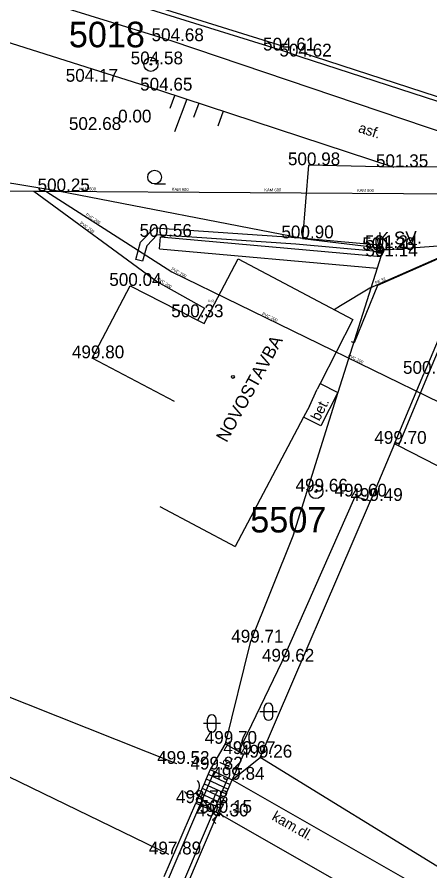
# Model space of a CAD drawing. Extents: x -668867 to -667827, y -1131943 to -1131019.
# Drawn here: x -668306.6 to -668282.4, y -1131620.9 to -1131570.8 of the extents above; entities that cross this region are included whole.
import ezdxf

# ---------------------------------------------------------------- set-up
doc = ezdxf.new("R2010")
doc.units = 0
for name, color, linetype in [('G_Bod_tecka', 7, 'Continuous'), ('G_Bod_vyska', 7, 'Continuous'), ('G_Bodove_pole', 7, 'Continuous'), ('G_Breh_Teren', 7, 'Continuous'), ('G_Budovy-znacky', 7, 'Continuous'), ('G_Budovy_Objekty', 7, 'Continuous'), ('G_Budovy_vstupy', 7, 'Continuous'), ('G_Cesty_Schody', 7, 'Continuous'), ('G_Plochy_zpevnene', 7, 'Continuous'), ('G_Ploty', 7, 'Continuous'), ('G_Ploty_vstupy', 7, 'Continuous'), ('G_Popisy_povrchu', 7, 'Continuous'), ('G_Poznamky_odkaz', 7, 'Continuous'), ('G_Site-kanalizace', 7, 'Continuous'), ('G_Site-Sloupy', 7, 'Continuous'), ('G_Vyskove_srafy', 7, 'Continuous'), ('G_Z_CHRANICKA-TEPLOVOD_kotovane', 7, 'Continuous'), ('G_Z_ELsilove_nadz_kotovane', 7, 'Continuous'), ('G_Z_KANAL_podz_kotovane', 7, 'Continuous'), ('G_Z_SPOJE_podz_geodeticky', 7, 'Continuous'), ('G_Z_SPOJE_podz_kotovane', 7, 'Continuous'), ('G_Z_SPOJE_podz_priblizne', 7, 'Continuous'), ('G_Z_VODA_podz_kotovane', 7, 'Continuous'), ('G_Zabradli_Svodidla', 7, 'Continuous'), ('G_Zelen-Znacky', 7, 'Continuous'), ('Vrstva 12', 7, 'Continuous'), ('Vrstva 13', 7, 'Continuous'), ('Vrstva 2', 7, 'Continuous'), ('Vrstva 26', 7, 'Continuous'), ('Vrstva 3', 7, 'Continuous'), ('Vrstva 4', 7, 'Continuous'), ('Vrstva 8', 7, 'Continuous')]:
    doc.layers.add(name, color=color, linetype=linetype)

msp = doc.modelspace()

# ---------------------------------------------------------------- linework, layer by layer
at = {"layer": 'G_Bod_tecka'}
for p, q in [((-668297.5, -1131572.23), (-668297.5, -1131572.23)), ((-668291.02, -1131572.78), (-668291.02, -1131572.78)), ((-668290, -1131573.13), (-668290, -1131573.13)), ((-668298.74, -1131573.59), (-668298.74, -1131573.59)), ((-668302.69, -1131574.61), (-668302.69, -1131574.61)), ((-668298.17, -1131575.13), (-668298.17, -1131575.13)), ((-668299.88, -1131577), (-668299.88, -1131577)), ((-668302.35, -1131577.44), (-668302.35, -1131577.44)), ((-668289.49, -1131579.51), (-668289.49, -1131579.51)), ((-668284.49, -1131579.62), (-668284.49, -1131579.62)), ((-668304.18, -1131581.04), (-668304.18, -1131581.04)), ((-668298.18, -1131583.71), (-668298.18, -1131583.71)), ((-668289.85, -1131583.8), (-668289.85, -1131583.8)), ((-668285.28, -1131584.49), (-668285.28, -1131584.49)), ((-668285.25, -1131584.86), (-668285.25, -1131584.86)), ((-668285.13, -1131584.37), (-668285.13, -1131584.37)), ((-668299.95, -1131586.59), (-668299.95, -1131586.59)), ((-668296.35, -1131588.43), (-668296.35, -1131588.43)), ((-668302.18, -1131590.84), (-668302.18, -1131590.84)), ((-668282.72, -1131591.75), (-668282.72, -1131591.75)), ((-668284.44, -1131595.86), (-668284.44, -1131595.86)), ((-668289.06, -1131598.66), (-668289.06, -1131598.66)), ((-668286.76, -1131598.95), (-668286.76, -1131598.95)), ((-668285.86, -1131599.21), (-668285.86, -1131599.21)), ((-668292.92, -1131607.52), (-668292.92, -1131607.52)), ((-668291.04, -1131608.64), (-668291.04, -1131608.64)), ((-668294.39, -1131613.46), (-668294.39, -1131613.46)), ((-668293.31, -1131614.06), (-668293.31, -1131614.06)), ((-668292.33, -1131614.27), (-668292.33, -1131614.27)), ((-668297.21, -1131614.64), (-668297.21, -1131614.64)), ((-668295.26, -1131614.97), (-668295.26, -1131614.97)), ((-668293.97, -1131615.57), (-668293.97, -1131615.57)), ((-668296.1, -1131616.94), (-668296.1, -1131616.94)), ((-668294.89, -1131617.72), (-668294.89, -1131617.72)), ((-668294.81, -1131617.51), (-668294.81, -1131617.51)), ((-668297.69, -1131619.95), (-668297.69, -1131619.95))]:
    msp.add_line(p, q, dxfattribs=at)
at = {"layer": 'G_Bodove_pole'}
for centre, radius in [((-668298.74, -1131573.59), 0.412), ((-668298.74, -1131573.59), 0.05), ((-668289.06, -1131598.66), 0.412), ((-668289.06, -1131598.66), 0.05)]:
    msp.add_circle(centre, radius, dxfattribs=at)
at = {"layer": 'G_Breh_Teren'}
for p, q in [((-668304.18, -1131581.04), (-668313.28, -1131579.52)), ((-668289.85, -1131583.8), (-668304.18, -1131581.04))]:
    msp.add_line(p, q, dxfattribs=at)
msp.add_lwpolyline([(-668297.69, -1131619.95), (-668307.08, -1131615.39), (-668316.46, -1131610.83), (-668321.53, -1131608.45), (-668329.23, -1131605.11), (-668337.01, -1131601.9), (-668340.19, -1131600.66), (-668345.82, -1131598.75), (-668354.38, -1131596.26), (-668362.99, -1131593.93), (-668371.08, -1131591.74)], dxfattribs=at)
at = {"layer": 'G_Budovy-znacky'}
msp.add_circle((-668293.93, -1131591.93), 0.0875, dxfattribs=at)
at = {"layer": 'G_Budovy_Objekty'}
for p, q in [((-668293.62, -1131585.01), (-668286.89, -1131588.57)), ((-668297.35, -1131593.38), (-668302.18, -1131590.84)), ((-668298.22, -1131599.54), (-668293.8, -1131601.88)), ((-668297.96, -1131621.25), (-668296.1, -1131616.94)), ((-668294.81, -1131617.51), (-668298.96, -1131627.18))]:
    msp.add_line(p, q, dxfattribs=at)
for points in [[(-668296.35, -1131588.43), (-668295.62, -1131588.8), (-668293.62, -1131585.01)], [(-668302.18, -1131590.84), (-668299.95, -1131586.59), (-668297.15, -1131588.02)], [(-668286.89, -1131588.57), (-668288.81, -1131592.32), (-668288.98, -1131592.65)], [(-668289.44, -1131593.64), (-668289.79, -1131594.3)], [(-668289.79, -1131594.3), (-668293.8, -1131601.88)]]:
    msp.add_lwpolyline(points, dxfattribs=at)
at = {"layer": 'G_Budovy_vstupy'}
for p, q in [((-668296.35, -1131588.43), (-668297.15, -1131588.02)), ((-668289.44, -1131593.64), (-668288.98, -1131592.65))]:
    msp.add_line(p, q, dxfattribs=at)
at = {"layer": 'G_Cesty_Schody'}
for p, q in [((-668297.5, -1131572.23), (-668314.35, -1131567)), ((-668315.47, -1131569.63), (-668298.17, -1131575.13))]:
    msp.add_line(p, q, dxfattribs=at)
for points in [[(-668295.37, -1131615.25), (-668295.49, -1131615.52)], [(-668295.26, -1131614.97), (-668295.37, -1131615.25)], [(-668295.37, -1131615.25), (-668294.09, -1131615.84)], [(-668295.26, -1131614.97), (-668293.97, -1131615.57)], [(-668295.61, -1131615.8), (-668295.73, -1131616.07)], [(-668295.49, -1131615.52), (-668295.61, -1131615.8)], [(-668295.61, -1131615.8), (-668294.33, -1131616.39)], [(-668295.49, -1131615.52), (-668294.21, -1131616.12)], [(-668294.21, -1131616.12), (-668294.09, -1131615.84)], [(-668294.09, -1131615.84), (-668293.97, -1131615.57)], [(-668295.85, -1131616.35), (-668295.96, -1131616.63)], [(-668295.73, -1131616.07), (-668295.85, -1131616.35)], [(-668295.85, -1131616.35), (-668294.57, -1131616.94)], [(-668295.73, -1131616.07), (-668294.45, -1131616.67)], [(-668294.45, -1131616.67), (-668294.33, -1131616.39)], [(-668294.33, -1131616.39), (-668294.21, -1131616.12)], [(-668295.96, -1131616.63), (-668296.1, -1131616.94)], [(-668295.96, -1131616.63), (-668294.69, -1131617.22)], [(-668294.57, -1131616.94), (-668294.45, -1131616.67)], [(-668296.1, -1131616.94), (-668294.81, -1131617.51)], [(-668294.81, -1131617.51), (-668294.69, -1131617.22)], [(-668294.69, -1131617.22), (-668294.57, -1131616.94)]]:
    msp.add_lwpolyline(points, dxfattribs=at)
at = {"layer": 'G_Plochy_zpevnene'}
for p, q in [((-668298.17, -1131575.13), (-668284.49, -1131579.62)), ((-668289.49, -1131579.51), (-668289.85, -1131583.8)), ((-668289.85, -1131583.8), (-668285.13, -1131584.37)), ((-668291.04, -1131608.64), (-668286.76, -1131598.95)), ((-668286.76, -1131598.95), (-668285.86, -1131599.21)), ((-668294.39, -1131613.46), (-668293.57, -1131613.91))]:
    msp.add_line(p, q, dxfattribs=at)
for points in [[(-668277.65, -1131578.66), (-668279.86, -1131578.2), (-668297.5, -1131572.23)], [(-668281.23, -1131579.62), (-668282.79, -1131579.61), (-668284.49, -1131579.62), (-668286.99, -1131579.56), (-668289.49, -1131579.51)], [(-668285.25, -1131584.86), (-668285.47, -1131585.55), (-668287.78, -1131592.84), (-668290.41, -1131601.28), (-668292.92, -1131607.52)], [(-668285.13, -1131584.37), (-668285.25, -1131584.86)], [(-668288.81, -1131592.32), (-668287.78, -1131592.84), (-668288.77, -1131594.81), (-668289.79, -1131594.3)], [(-668292.92, -1131607.52), (-668294.39, -1131613.46)], [(-668293.57, -1131613.91), (-668291.04, -1131608.64)], [(-668294.39, -1131613.46), (-668295.26, -1131614.97)], [(-668293.57, -1131613.91), (-668293.31, -1131614.06)], [(-668293.31, -1131614.06), (-668293.97, -1131615.57)], [(-668293.97, -1131615.57), (-668282.89, -1131621.91)], [(-668294.81, -1131617.51), (-668287.32, -1131621.79)]]:
    msp.add_lwpolyline(points, dxfattribs=at)
at = {"layer": 'G_Ploty'}
for p, q in [((-668290.95, -1131572.54), (-668315.71, -1131564.82)), ((-668315.78, -1131565.06), (-668291.02, -1131572.78)), ((-668290, -1131573.13), (-668278.48, -1131576.88)), ((-668278.49, -1131576.62), (-668289.92, -1131572.89)), ((-668298.24, -1131584.41), (-668298.18, -1131583.71)), ((-668298.18, -1131583.71), (-668285.25, -1131584.86)), ((-668298.24, -1131584.41), (-668285.47, -1131585.55)), ((-668279.64, -1131584.38), (-668282.72, -1131591.75)), ((-668282.49, -1131591.85), (-668279.45, -1131584.57)), ((-668284.44, -1131595.86), (-668282.72, -1131591.75)), ((-668284.22, -1131595.98), (-668282.49, -1131591.85)), ((-668284.22, -1131595.98), (-668284.44, -1131595.86)), ((-668275.6, -1131600.39), (-668284.22, -1131595.98)), ((-668292.33, -1131614.27), (-668285.86, -1131599.21)), ((-668297.21, -1131614.64), (-668308.73, -1131610.06)), ((-668293.97, -1131615.57), (-668292.33, -1131614.27)), ((-668264.03, -1131631.7), (-668292.33, -1131614.27))]:
    msp.add_line(p, q, dxfattribs=at)
at = {"layer": 'G_Ploty_vstupy'}
for p, q in [((-668291.02, -1131572.78), (-668290, -1131573.13)), ((-668284.44, -1131595.86), (-668285.86, -1131599.21))]:
    msp.add_line(p, q, dxfattribs=at)
at = {"layer": 'G_Site-kanalizace'}
for p, q in [((-668296.071, -1131616.313), (-668294.89, -1131617.72)), ((-668295.12, -1131617.913), (-668294.89, -1131617.72)), ((-668294.927, -1131618.143), (-668295.12, -1131617.913)), ((-668294.66, -1131617.527), (-668294.89, -1131617.72)), ((-668294.467, -1131617.757), (-668294.66, -1131617.527))]:
    msp.add_line(p, q, dxfattribs=at)
msp.add_arc((-668296.393, -1131615.931), 0.5, 220.0084, 40.0084, dxfattribs=at)
at = {"layer": 'G_Site-Sloupy'}
msp.add_circle((-668285.28, -1131584.49), 0.2, dxfattribs=at)
for radius in [0.18, 0.16, 0.14, 0.12, 0.1, 0.08, 0.06, 0.04, 0.02]:
    msp.add_arc((-668285.28, -1131584.49), radius, 180, 0, dxfattribs=at)
at = {"layer": 'G_Vyskove_srafy'}
for p, q in [((-668297.36, -1131575.43), (-668297.63, -1131576.18)), ((-668296.63, -1131575.63), (-668297.35, -1131577.56)), ((-668295.92, -1131575.87), (-668296.23, -1131576.7)), ((-668294.49, -1131576.34), (-668294.82, -1131577.22))]:
    msp.add_line(p, q, dxfattribs=at)
at = {"layer": 'G_Z_CHRANICKA-TEPLOVOD_kotovane'}
msp.add_lwpolyline([(-668299.624, -1131585.032), (-668299.339, -1131584.027), (-668298.519, -1131583.174), (-668290.194, -1131583.751), (-668285.594, -1131584.153), (-668285.208, -1131584.302), (-668285.352, -1131584.676), (-668285.686, -1131584.547), (-668290.226, -1131584.149), (-668298.361, -1131583.586), (-668298.981, -1131584.233), (-668299.239, -1131585.141)], close=True, dxfattribs=at)
at = {"layer": 'G_Z_ELsilove_nadz_kotovane'}
for points in [[(-668285.28, -1131584.49), (-668266.27, -1131583.06)], [(-668285.28, -1131584.49), (-668285.452, -1131583.853)]]:
    msp.add_lwpolyline(points, dxfattribs=at)
at = {"layer": 'G_Z_KANAL_podz_kotovane'}
for points in [[(-668311.3, -1131581), (-668305.6, -1131581.03), (-668304.9, -1131581.04), (-668280.93, -1131581.18)], [(-668305.6, -1131581.03), (-668298.35, -1131586.35), (-668295.59, -1131587.89), (-668296, -1131588.62)], [(-668304.9, -1131581.04), (-668297.51, -1131585.77), (-668273.92, -1131597.27)]]:
    msp.add_lwpolyline(points, dxfattribs=at)
at = {"layer": 'G_Z_SPOJE_podz_geodeticky'}
msp.add_lwpolyline([(-668265.31, -1131577.72), (-668285.44, -1131586.57), (-668286.81, -1131589.93), (-668286.97, -1131589.87)], dxfattribs=at)
at = {"layer": 'G_Z_SPOJE_podz_kotovane'}
msp.add_lwpolyline([(-668265.31, -1131577.72), (-668285.44, -1131586.57), (-668286.81, -1131589.93), (-668286.97, -1131589.87)], dxfattribs=at)
at = {"layer": 'G_Z_SPOJE_podz_priblizne'}
msp.add_lwpolyline([(-668265.31, -1131577.72), (-668285.44, -1131586.57), (-668286.81, -1131589.93), (-668286.97, -1131589.87)], dxfattribs=at)
at = {"layer": 'G_Z_VODA_podz_kotovane'}
msp.add_lwpolyline([(-668256.28, -1131582.77), (-668256.28, -1131582.78), (-668256.27, -1131582.89), (-668256.47, -1131583.21), (-668257.45, -1131584.8), (-668257.85, -1131585.41), (-668262.13, -1131582.86), (-668266.77, -1131579.97), (-668268.19, -1131579.22), (-668272.51, -1131581.1), (-668279.9, -1131584.09), (-668285.9, -1131586.73), (-668287.61, -1131587.77), (-668287.98, -1131587.99)], dxfattribs=at)
at = {"layer": 'G_Zabradli_Svodidla'}
for p, q in [((-668295.02, -1131615.08), (-668300.82, -1131628.65)), ((-668294.22, -1131615.45), (-668299.99, -1131628.96))]:
    msp.add_line(p, q, dxfattribs=at)
at = {"layer": 'G_Zelen-Znacky'}
msp.add_line((-668298.522, -1131580.61), (-668297.872, -1131580.607), dxfattribs=at)
for points in [[(-668292.09, -1131611.83), (-668292.09, -1131611.33)], [(-668291.59, -1131611.83), (-668291.59, -1131611.33)], [(-668291.34, -1131611.58), (-668292.34, -1131611.58)], [(-668294.66, -1131612.27), (-668295.66, -1131612.27)], [(-668295.41, -1131612.52), (-668295.41, -1131612.02)], [(-668294.91, -1131612.52), (-668294.91, -1131612.02)]]:
    msp.add_lwpolyline(points, dxfattribs=at)
msp.add_circle((-668298.522, -1131580.207), 0.403, dxfattribs=at)
for centre, start, end in [((-668291.84, -1131611.33), 0, 180), ((-668295.16, -1131612.02), 0, 180), ((-668291.84, -1131611.83), 180, 0), ((-668295.16, -1131612.52), 180, 0)]:
    msp.add_arc(centre, 0.25, start, end, dxfattribs=at)
at = {"layer": 'Vrstva 12'}
msp.add_lwpolyline([(-668311.3, -1131581), (-668305.6, -1131581.034), (-668304.9, -1131581.038), (-668280.93, -1131581.18)], dxfattribs=at)
at = {"layer": 'Vrstva 13'}
for points in [[(-668305.6, -1131581.034), (-668298.354, -1131586.347), (-668295.594, -1131587.89), (-668296.003, -1131588.617)], [(-668304.9, -1131581.038), (-668297.512, -1131585.765), (-668273.923, -1131597.273)]]:
    msp.add_lwpolyline(points, dxfattribs=at)
at = {"layer": 'Vrstva 26'}
msp.add_lwpolyline([(-668256.281, -1131582.769), (-668256.28, -1131582.78), (-668256.27, -1131582.89), (-668256.469, -1131583.211), (-668257.45, -1131584.8), (-668257.85, -1131585.41), (-668262.13, -1131582.86), (-668266.77, -1131579.97), (-668268.19, -1131579.22), (-668272.51, -1131581.1), (-668279.9, -1131584.09), (-668285.9, -1131586.73), (-668287.61, -1131587.77), (-668287.979, -1131587.994)], dxfattribs=at)
at = {"layer": 'Vrstva 8'}
msp.add_line((-668295.594, -1131587.89), (-668295.594, -1131587.89), dxfattribs=at)

# ---------------------------------------------------------------- texts
at = {"layer": 'G_Bod_vyska'}
for s, p in [('504.68', (-668298.699, -1131572.23)), ('504.61', (-668292.158, -1131572.78)), ('504.58', (-668299.923, -1131573.59)), ('504.62', (-668291.199, -1131573.13)), ('504.17', (-668303.734, -1131574.61)), ('504.65', (-668299.369, -1131575.13)), ('0.00', (-668300.66, -1131577)), ('502.68', (-668303.549, -1131577.44)), ('500.98', (-668290.699, -1131579.51)), ('501.35', (-668285.534, -1131579.62)), ('500.25', (-668305.387, -1131581.04)), ('500.56', (-668299.401, -1131583.71)), ('500.90', (-668291.081, -1131583.8)), ('501.26', (-668286.338, -1131584.49)), ('501.24', (-668286.174, -1131584.37)), ('501.14', (-668286.152, -1131584.86)), ('500.04', (-668301.179, -1131586.59)), ('500.33', (-668297.547, -1131588.43)), ('499.80', (-668303.37, -1131590.84)), ('500.30', (-668283.949, -1131591.75)), ('499.70', (-668285.63, -1131595.86)), ('499.66', (-668290.253, -1131598.66)), ('499.60', (-668287.963, -1131598.95)), ('499.49', (-668287.03, -1131599.21)), ('499.71', (-668294.026, -1131607.52)), ('499.62', (-668292.222, -1131608.64)), ('499.70', (-668295.58, -1131613.46)), ('499.67', (-668294.492, -1131614.06)), ('499.52', (-668298.368, -1131614.64)), ('499.26', (-668293.512, -1131614.27)), ('499.82', (-668296.418, -1131614.97)), ('499.84', (-668295.138, -1131615.57)), ('498.78', (-668297.266, -1131616.94)), ('500.15', (-668295.876, -1131617.51)), ('497.30', (-668296.078, -1131617.72)), ('497.89', (-668298.858, -1131619.95))]:
    msp.add_text(s, height=0.75, dxfattribs=at).set_placement(p)
at = {"layer": 'G_Bodove_pole'}
for s, p in [('5018', (-668303.552, -1131572.59)), ('5507', (-668292.908, -1131601.06))]:
    msp.add_text(s, height=1.5, dxfattribs=at).set_placement(p)
at = {"layer": 'G_Popisy_povrchu'}
for s, rotation, p in [('asf.', 341.8293, (-668286.611, -1131577.558)), ('bet.', 63.3187, (-668288.857, -1131594.559)), ('b.', 66.5042, (-668294.166, -1131614.885)), ('kam.dl.', 330.2024, (-668291.689, -1131617.889))]:
    msp.add_text(s, height=0.6, rotation=rotation, dxfattribs=at).set_placement(p)
at = {"layer": 'G_Poznamky_odkaz'}
for s, rotation, p in [('K.SV.', 1.9858, (-668285.405, -1131584.199)), ('NOVOSTAVBA', 61.2668, (-668294.296, -1131595.822))]:
    msp.add_text(s, height=0.75, rotation=rotation, dxfattribs=at).set_placement(p)
at = {"layer": 'Vrstva 2'}
msp.add_text('0 (0)', height=0.1316, dxfattribs=at).set_placement((-668295.388, -1131587.537))
at = {"layer": 'Vrstva 3'}
for s, rotation, p in [('KAM 600', 359.6622, (-668302.955, -1131580.979)), ('KAM 600', 359.6622, (-668297.521, -1131581.011)), ('KAM 600', 359.6622, (-668292.085, -1131581.043)), ('KAM 600', 359.6622, (-668286.651, -1131581.075)), ('PVC 200', 327.4037, (-668302.586, -1131582.456)), ('PVC 200', 323.7215, (-668302.918, -1131582.935)), ('PVC 200', 330.5756, (-668297.561, -1131585.642)), ('PVC 200', 327.1157, (-668298.404, -1131586.214)), ('PVC 200', 333.9821, (-668292.233, -1131588.282)), ('PVC 200', 333.9821, (-668287.197, -1131590.738))]:
    msp.add_text(s, height=0.1755, rotation=rotation, dxfattribs=at).set_placement(p)
at = {"layer": 'Vrstva 4'}
msp.add_text('PE 32', height=0.1755, rotation=23.7468, dxfattribs=at).set_placement((-668285.537, -1131586.503))

doc.saveas('drawing.dxf')
